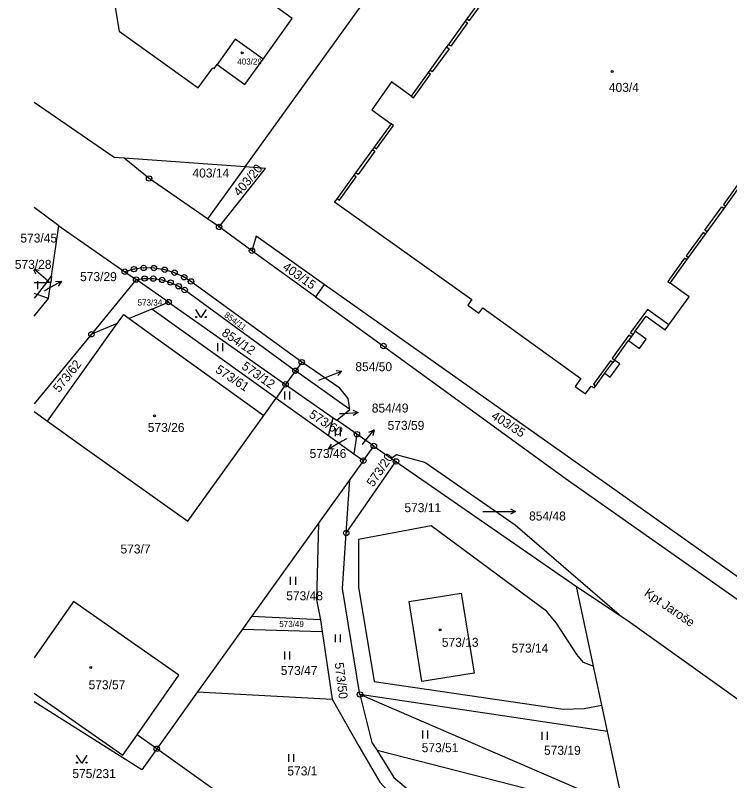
# Model space of a CAD drawing. Extents: x -737240 to -735272, y -1119606 to -1117878.
# Drawn here: x -737236.9 to -737101.6, y -1118720.4 to -1118575.4 of the extents above; entities that cross this region are included whole.
import ezdxf

# ---------------------------------------------------------------- set-up
doc = ezdxf.new("R2010")
doc.units = 0
for name, color, linetype in [('Level 1', 7, 'Continuous'), ('Level 15', 7, 'Continuous'), ('Level 16', 7, 'Continuous'), ('Level 18', 7, 'Continuous'), ('Level 19', 7, 'Continuous'), ('Level 25', 7, 'Continuous'), ('Level 4', 7, 'Continuous')]:
    doc.layers.add(name, color=color, linetype=linetype)

msp = doc.modelspace()

# ---------------------------------------------------------------- linework, layer by layer
at = {"layer": 'Level 1'}
for p, q in [((-737193.31, -1118604.16), (-737133.07, -1118520.39)), ((-737148.15, -1118571.71), (-737151.32, -1118576.1)), ((-737151.64, -1118576.55), (-737154.84, -1118580.96)), ((-737151.32, -1118576.1), (-737151.64, -1118576.55)), ((-737154.84, -1118580.96), (-737155.18, -1118581.42)), ((-737155.18, -1118581.42), (-737158.35, -1118585.81)), ((-737158.68, -1118586.26), (-737161.91, -1118590.73)), ((-737158.35, -1118585.81), (-737158.68, -1118586.26)), ((-737165.69, -1118595.96), (-737168.9, -1118600.4)), ((-737169.23, -1118600.85), (-737172.41, -1118605.26)), ((-737168.9, -1118600.4), (-737169.23, -1118600.85)), ((-737193.31, -1118604.16), (-737216.26, -1118602.47)), ((-737193.31, -1118604.16), (-737200.44, -1118614.01)), ((-737172.73, -1118605.71), (-737175.92, -1118610.13)), ((-737172.41, -1118605.26), (-737172.73, -1118605.71)), ((-737102.3, -1118611.56), (-737099.13, -1118607.18)), ((-737102.63, -1118612.02), (-737102.3, -1118611.56)), ((-737228.65, -1118615.3), (-737233.313, -1118611.841)), ((-737105.82, -1118616.43), (-737102.63, -1118612.02)), ((-737198.27, -1118615.51), (-737200.44, -1118614.01)), ((-737230, -1118624.86), (-737228.65, -1118615.3)), ((-737228.65, -1118615.3), (-737216.14, -1118623.99)), ((-737192.05, -1118620.02), (-737198.27, -1118615.51)), ((-737109.33, -1118621.28), (-737106.16, -1118616.89)), ((-737106.16, -1118616.89), (-737105.82, -1118616.43)), ((-737180.02, -1118628.74), (-737192.05, -1118620.02)), ((-737112.85, -1118626.14), (-737109.66, -1118621.73)), ((-737109.66, -1118621.73), (-737109.33, -1118621.28)), ((-737216.14, -1118623.99), (-737213.99, -1118625.48)), ((-737233.313, -1118626.039), (-737230.94, -1118626.03)), ((-737230.94, -1118626.03), (-737232.75, -1118628.29)), ((-737230.94, -1118626.03), (-737230, -1118624.86)), ((-737230.16, -1118626.04), (-737230.94, -1118626.03)), ((-737230.6, -1118629.1), (-737230.16, -1118626.04)), ((-737230, -1118624.86), (-737230.16, -1118626.04)), ((-737213.99, -1118625.48), (-737222.45, -1118635.85)), ((-737207.85, -1118629.75), (-737213.99, -1118625.48)), ((-737178.34, -1118626.41), (-737180.02, -1118628.74)), ((-737233.313, -1118628.075), (-737232.75, -1118628.29)), ((-737232.75, -1118628.29), (-737233.313, -1118628.991)), ((-737230.6, -1118629.1), (-737232.75, -1118628.29)), ((-737211.04, -1118631.08), (-737207.85, -1118629.75)), ((-737207.85, -1118629.75), (-737185.68, -1118645.33)), ((-737211.04, -1118631.08), (-737215.31, -1118632.86)), ((-737187.47, -1118647.95), (-737211.04, -1118631.08)), ((-737230.77, -1118652.31), (-737217.55, -1118633.8)), ((-737217.55, -1118633.8), (-737222.45, -1118635.85)), ((-737222.45, -1118635.85), (-737233.313, -1118649.023)), ((-737123.4, -1118640.72), (-737120.73, -1118637.03)), ((-737182.62, -1118641.13), (-737183.8, -1118642.75)), ((-737183.8, -1118642.75), (-737185.68, -1118645.33)), ((-737173.49, -1118650.1), (-737183.8, -1118642.75)), ((-737126.92, -1118645.59), (-737125.21, -1118643.22)), ((-737185.68, -1118645.33), (-737187.47, -1118647.95)), ((-737185.68, -1118645.33), (-737176.64, -1118651.66)), ((-737189.81, -1118651.21), (-737187.47, -1118647.95)), ((-737187.47, -1118647.95), (-737177.56, -1118655.03)), ((-737233.313, -1118650.471), (-737230.77, -1118652.31)), ((-737175.96, -1118652.13), (-737173.49, -1118650.1)), ((-737177.56, -1118655.03), (-737176.64, -1118651.66)), ((-737176.64, -1118651.66), (-737175.96, -1118652.13)), ((-737172.17, -1118654.78), (-737175.96, -1118652.13)), ((-737177.56, -1118655.03), (-737172.72, -1118658.5)), ((-737172.17, -1118654.78), (-737172.72, -1118658.5)), ((-737168.96, -1118657.01), (-737172.17, -1118654.78)), ((-737170.94, -1118659.78), (-737168.96, -1118657.01)), ((-737168.96, -1118657.01), (-737165.59, -1118659.35)), ((-737172.72, -1118658.5), (-737170.94, -1118659.78)), ((-737165.59, -1118659.35), (-737164.77, -1118659.92)), ((-737174.18, -1118673.49), (-737164.77, -1118659.92)), ((-737170.94, -1118659.78), (-737173.51, -1118663.36)), ((-737164.77, -1118659.92), (-737130.56, -1118683.64)), ((-737173.51, -1118663.36), (-737179.44, -1118671.64)), ((-737174.18, -1118673.49), (-737173.51, -1118663.36)), ((-737179.44, -1118671.64), (-737192.11, -1118689.31)), ((-737130.56, -1118683.64), (-737122.52, -1118688.97)), ((-737127.35, -1118698.73), (-737130.56, -1118683.64)), ((-737192.11, -1118689.31), (-737193.83, -1118691.71)), ((-737179.08, -1118689.92), (-737192.11, -1118689.31)), ((-737179.08, -1118689.92), (-737178.75, -1118692.14)), ((-737193.83, -1118691.71), (-737202.33, -1118703.57)), ((-737193.83, -1118691.71), (-737178.75, -1118692.14)), ((-737178.75, -1118692.14), (-737176.87, -1118704.97)), ((-737125.78, -1118706.13), (-737127.35, -1118698.73)), ((-737202.33, -1118703.57), (-737210.07, -1118714.36)), ((-737202.33, -1118703.57), (-737176.87, -1118704.97)), ((-737124.73, -1118711.06), (-737171.59, -1118704.08)), ((-737121.62, -1118725.66), (-737171.59, -1118704.08)), ((-737124.73, -1118711.06), (-737125.78, -1118706.13)), ((-737210.07, -1118714.36), (-737213.79, -1118711.71)), ((-737121.62, -1118725.66), (-737124.73, -1118711.06)), ((-737189.33, -1118729.14), (-737210.07, -1118714.36)), ((-737121.41, -1118726.65), (-737168.35, -1118714.71))]:
    msp.add_line(p, q, dxfattribs=at)
for points in [[(-737189.93, -1118583.71), (-737184.41, -1118576.03), (-737199.69, -1118564.94), (-737200.12, -1118562.3), (-737186.12, -1118560.03), (-737188.01, -1118548.39), (-737182.85, -1118547.56), (-737186.18, -1118526.96), (-737215.02, -1118531.57), (-737214.4, -1118535.42), (-737219.27, -1118536.23), (-737216.7, -1118552.51), (-737217.91, -1118552.7), (-737217.86, -1118553), (-737221.24, -1118553.54), (-737219.2, -1118566.32), (-737221.63, -1118570.06), (-737218.17, -1118572.81), (-737217.18, -1118578.42), (-737202.24, -1118589.17), (-737199.46, -1118585.37), (-737199.23, -1118585.53), (-737198.64, -1118584.72)], [(-737189.93, -1118583.71), (-737195.2, -1118579.93), (-737198.64, -1118584.72)], [(-737198.64, -1118584.72), (-737193.38, -1118588.51), (-737189.93, -1118583.71)], [(-737161.91, -1118590.73), (-737165.62, -1118588.06), (-737169.31, -1118593.32), (-737165.69, -1118595.96)], [(-737216.26, -1118602.47), (-737218.12, -1118602.34), (-737233.313, -1118591.922)], [(-737200.44, -1118614.01), (-737211.53, -1118606.34), (-737216.26, -1118602.47)], [(-737198.27, -1118615.51), (-737189.47, -1118604.44), (-737193.31, -1118604.16)], [(-737175.92, -1118610.13), (-737176.43, -1118610.79), (-737150.4, -1118629.29), (-737151.16, -1118630.34), (-737149.05, -1118631.87), (-737148.29, -1118630.81), (-737129.75, -1118644.23), (-737130.82, -1118645.71), (-737128.86, -1118647.13), (-737127.79, -1118645.65), (-737127.24, -1118645.99), (-737126.92, -1118645.59)], [(-737178.34, -1118626.41), (-737191.23, -1118617.29), (-737192.05, -1118620.02)], [(-737182.62, -1118641.13), (-737203.6, -1118625.84), (-737204.87, -1118625.05), (-737206.7, -1118624.18), (-737208.55, -1118623.62), (-737210.62, -1118623.3), (-737212.56, -1118623.28), (-737214.39, -1118623.51), (-737216.14, -1118623.99)], [(-737213.99, -1118625.48), (-737212.39, -1118625.28), (-737210.72, -1118625.3), (-737209.06, -1118625.55), (-737207.46, -1118626.04), (-737205.93, -1118626.74), (-737204.78, -1118627.46), (-737183.8, -1118642.75)], [(-737113.11, -1118634.05), (-737109.26, -1118628.74), (-737112.85, -1118626.14)], [(-737096.44, -1118684.35), (-737124.41, -1118664.58), (-737178.34, -1118626.41)], [(-737233.313, -1118632.413), (-737230.6, -1118629.1)], [(-737180.02, -1118628.74), (-737167.14, -1118638.07), (-737132.69, -1118663.08), (-737098.41, -1118687.2), (-737097.57, -1118687.8)], [(-737217.55, -1118633.8), (-737216.34, -1118632.11), (-737215.31, -1118632.86)], [(-737215.31, -1118632.86), (-737209.82, -1118636.84), (-737189.81, -1118651.21)], [(-737119.44, -1118635.25), (-737117.38, -1118632.4), (-737113.79, -1118635), (-737113.11, -1118634.05)], [(-737120.73, -1118637.03), (-737118.64, -1118638.54), (-737117.35, -1118636.76), (-737119.44, -1118635.25)], [(-737125.21, -1118643.22), (-737124.17, -1118643.97), (-737122.36, -1118641.47), (-737123.4, -1118640.72)], [(-737173.49, -1118650.1), (-737173.82, -1118648.01), (-737175.42, -1118646.04), (-737182.62, -1118641.13)], [(-737230.77, -1118652.31), (-737224.24, -1118656.99), (-737204.2, -1118671.26), (-737189.81, -1118651.21)], [(-737122.52, -1118688.97), (-737142.19, -1118671.99), (-737159.33, -1118660.12), (-737164.65, -1118658.71), (-737165.59, -1118659.35)], [(-737179.44, -1118671.64), (-737179.82, -1118686.15), (-737179.08, -1118689.92)], [(-737127.35, -1118698.73), (-737127.46, -1118698.72), (-737129.24, -1118698.01), (-737130.52, -1118696.5), (-737134.38, -1118690.56), (-737136.28, -1118688.27), (-737158.09, -1118672.16), (-737171.87, -1118674.72), (-737171.85, -1118683.75), (-737168.9, -1118701.59), (-737133.1, -1118706.86), (-737129.1, -1118706.7), (-737125.78, -1118706.13)], [(-737171.59, -1118704.08), (-737174.88, -1118684.02), (-737174.18, -1118673.49)], [(-737162.29, -1118686.44), (-737152.41, -1118684.86), (-737149.95, -1118700.01), (-737159.89, -1118701.64), (-737162.29, -1118686.44)], [(-737213.79, -1118711.71), (-737205.9, -1118700.43), (-737225.84, -1118686.47), (-737233.313, -1118697.141)], [(-737122.52, -1118688.97), (-737120.76, -1118690.14), (-737045.38, -1118744)], [(-737233.313, -1118703.828), (-737216.51, -1118715.6), (-737213.79, -1118711.71)], [(-737171.59, -1118704.08), (-737169.34, -1118713.14), (-737168.35, -1118714.71)], [(-737210.07, -1118714.36), (-737212.92, -1118718.33), (-737233.313, -1118705.441)], [(-737176.87, -1118704.97), (-737171.79, -1118713.84), (-737167.84, -1118720.71), (-737164.67, -1118724.07)], [(-737168.35, -1118714.71), (-737165.14, -1118719.81), (-737158.2, -1118725.63)]]:
    msp.add_lwpolyline(points, dxfattribs=at)
at = {"layer": 'Level 16'}
for points in [[(-737233.313, -1118623.485), (-737232.321, -1118623.721)], [(-737230.49, -1118625.91), (-737231.11, -1118625.39), (-737233.313, -1118623.542)], [(-737232.964, -1118624.488), (-737233.313, -1118623.683)], [(-737231.33, -1118627.6), (-737230.75, -1118627.27), (-737228.146, -1118625.78)], [(-737229.263, -1118625.843), (-737228.146, -1118625.78), (-737228.766, -1118626.71)], [(-737179.4, -1118644.52), (-737177.81, -1118643.91), (-737175.007, -1118642.84)], [(-737176.12, -1118642.729), (-737175.007, -1118642.84), (-737175.763, -1118643.664)], [(-737175.48, -1118650.86), (-737174.9, -1118650.83), (-737171.904, -1118650.673)], [(-737172.929, -1118650.226), (-737171.904, -1118650.673), (-737172.877, -1118651.225)], [(-737171.11, -1118656.71), (-737170.78, -1118656.29), (-737168.904, -1118653.949)], [(-737169.92, -1118654.417), (-737168.904, -1118653.949), (-737169.139, -1118655.042)], [(-737174.16, -1118655.65), (-737174.96, -1118656.1), (-737177.571, -1118657.578)], [(-737176.454, -1118657.52), (-737177.571, -1118657.578), (-737176.947, -1118656.65)], [(-737148.34, -1118669.42), (-737145.1, -1118669.42), (-737142.1, -1118669.425)], [(-737143.099, -1118668.923), (-737142.1, -1118669.425), (-737143.101, -1118669.923)]]:
    msp.add_lwpolyline(points, dxfattribs=at)
at = {"layer": 'Level 25'}
for p, q in [((-737232.575, -1118627.315), (-737232.575, -1118625.815)), ((-737198.577, -1118637.525), (-737198.577, -1118639.025)), ((-737197.555, -1118639.025), (-737197.555, -1118637.525)), ((-737185.877, -1118646.695), (-737185.877, -1118648.195)), ((-737184.855, -1118648.195), (-737184.855, -1118646.695)), ((-737176.277, -1118653.655), (-737176.277, -1118655.155)), ((-737175.255, -1118655.155), (-737175.255, -1118653.655)), ((-737184.777, -1118681.795), (-737184.777, -1118683.295)), ((-737183.755, -1118683.295), (-737183.755, -1118681.795)), ((-737176.297, -1118692.695), (-737176.297, -1118694.195)), ((-737175.275, -1118694.195), (-737175.275, -1118692.695)), ((-737185.867, -1118695.945), (-737185.867, -1118697.445)), ((-737184.845, -1118697.445), (-737184.845, -1118695.945)), ((-737159.727, -1118710.905), (-737159.727, -1118712.405)), ((-737158.705, -1118712.405), (-737158.705, -1118710.905)), ((-737137.107, -1118711.175), (-737137.107, -1118712.675)), ((-737136.085, -1118712.675), (-737136.085, -1118711.175)), ((-737185.117, -1118715.355), (-737185.117, -1118716.855)), ((-737184.095, -1118716.855), (-737184.095, -1118715.355))]:
    msp.add_line(p, q, dxfattribs=at)
for points in [[(-737200.7, -1118631.18), (-737201.7, -1118632.68), (-737202.7, -1118631.18)], [(-737223.29, -1118715.59), (-737224.29, -1118717.09), (-737225.29, -1118715.59)]]:
    msp.add_lwpolyline(points, dxfattribs=at)
for centre in [(-737202.6, -1118632.58), (-737200.8, -1118632.58), (-737225.19, -1118716.99), (-737223.39, -1118716.99)]:
    msp.add_circle(centre, 0.1, dxfattribs=at)
for centre, major_axis in [((-737193.89, -1118582.52), (0.18, 0)), ((-737123.81, -1118586.06), (0.18, 0)), ((-737211.53, -1118606.34), (0.516, 0)), ((-737211.53, -1118606.34), (0.0375, 0)), ((-737198.27, -1118615.51), (0.516, 0)), ((-737198.27, -1118615.51), (0.0375, 0)), ((-737192.05, -1118620.02), (0.516, 0)), ((-737192.05, -1118620.02), (0.0375, 0)), ((-737214.39, -1118623.51), (0.516, 0)), ((-737212.56, -1118623.28), (0.516, 0)), ((-737212.56, -1118623.28), (0.0375, 0)), ((-737210.62, -1118623.3), (0.516, 0)), ((-737210.62, -1118623.3), (0.0375, 0)), ((-737208.55, -1118623.62), (0.516, 0)), ((-737216.14, -1118623.99), (0.516, 0)), ((-737216.14, -1118623.99), (0.0375, 0)), ((-737214.39, -1118623.51), (0.0375, 0)), ((-737212.39, -1118625.28), (0.516, 0)), ((-737210.72, -1118625.3), (0.516, 0)), ((-737208.55, -1118623.62), (0.0375, 0)), ((-737206.7, -1118624.18), (0.516, 0)), ((-737206.7, -1118624.18), (0.0375, 0)), ((-737204.87, -1118625.05), (0.516, 0)), ((-737213.99, -1118625.48), (0.516, 0)), ((-737213.99, -1118625.48), (0.0375, 0)), ((-737212.39, -1118625.28), (0.0375, 0)), ((-737210.72, -1118625.3), (0.0375, 0)), ((-737209.06, -1118625.55), (0.516, 0)), ((-737209.06, -1118625.55), (0.0375, 0)), ((-737207.46, -1118626.04), (0.516, 0)), ((-737207.46, -1118626.04), (0.0375, 0)), ((-737205.93, -1118626.74), (0.516, 0)), ((-737204.87, -1118625.05), (0.0375, 0)), ((-737203.6, -1118625.84), (0.516, 0)), ((-737203.6, -1118625.84), (0.0375, 0)), ((-737205.93, -1118626.74), (0.0375, 0)), ((-737204.78, -1118627.46), (0.516, 0)), ((-737204.78, -1118627.46), (0.0375, 0)), ((-737207.85, -1118629.75), (0.516, 0)), ((-737207.85, -1118629.75), (0.0375, 0)), ((-737222.45, -1118635.85), (0.516, 0)), ((-737222.45, -1118635.85), (0.0375, 0)), ((-737167.14, -1118638.07), (0.516, 0)), ((-737167.14, -1118638.07), (0.0375, 0)), ((-737182.62, -1118641.13), (0.516, 0)), ((-737182.62, -1118641.13), (0.0375, 0)), ((-737183.8, -1118642.75), (0.516, 0)), ((-737183.8, -1118642.75), (0.0375, 0)), ((-737185.68, -1118645.33), (0.516, 0)), ((-737185.68, -1118645.33), (0.0375, 0)), ((-737210.5, -1118651.31), (0.18, 0)), ((-737172.17, -1118654.78), (0.516, 0)), ((-737172.17, -1118654.78), (0.0375, 0)), ((-737168.96, -1118657.01), (0.516, 0)), ((-737168.96, -1118657.01), (0.0375, 0)), ((-737170.94, -1118659.78), (0.516, 0)), ((-737164.77, -1118659.92), (0.516, 0)), ((-737170.94, -1118659.78), (0.0375, 0)), ((-737164.77, -1118659.92), (0.0375, 0)), ((-737174.18, -1118673.49), (0.516, 0)), ((-737174.18, -1118673.49), (0.0375, 0)), ((-737156.42, -1118691.82), (0.18, 0)), ((-737222.59, -1118698.98), (0.18, 0)), ((-737171.59, -1118704.08), (0.516, 0)), ((-737171.59, -1118704.08), (0.0375, 0)), ((-737210.07, -1118714.36), (0.516, 0)), ((-737210.07, -1118714.36), (0.0375, 0))]:
    msp.add_ellipse(centre, major_axis=major_axis, ratio=0.9848078, dxfattribs=at)
at = {"layer": 'Level 4'}
for p, q in [((-737120.21, -1118636.32), (-737120.73, -1118637.03)), ((-737119.88, -1118635.87), (-737120.21, -1118636.32)), ((-737119.44, -1118635.25), (-737119.88, -1118635.87)), ((-737123.4, -1118640.72), (-737123.72, -1118641.17)), ((-737125.21, -1118643.22), (-737123.72, -1118641.17))]:
    msp.add_line(p, q, dxfattribs=at)
for points in [[(-737151.32, -1118576.1), (-737150.87, -1118576.42), (-737147.7, -1118572.04), (-737148.15, -1118571.71)], [(-737151.64, -1118576.55), (-737151.2, -1118576.88), (-737154.39, -1118581.29), (-737154.84, -1118580.96)], [(-737155.18, -1118581.42), (-737154.72, -1118581.75), (-737157.9, -1118586.14), (-737158.35, -1118585.81)], [(-737161.91, -1118590.73), (-737161.46, -1118591.06), (-737158.23, -1118586.59), (-737158.68, -1118586.26)], [(-737168.9, -1118600.4), (-737168.45, -1118600.73), (-737165.24, -1118596.29), (-737165.69, -1118595.96)], [(-737169.23, -1118600.85), (-737168.77, -1118601.18), (-737171.95, -1118605.59), (-737172.41, -1118605.26)], [(-737175.92, -1118610.13), (-737175.47, -1118610.45), (-737172.28, -1118606.03), (-737172.73, -1118605.71)], [(-737099.13, -1118607.18), (-737099.57, -1118606.86), (-737102.75, -1118611.24), (-737102.3, -1118611.56)], [(-737105.82, -1118616.43), (-737106.27, -1118616.11), (-737103.07, -1118611.7), (-737102.63, -1118612.02)], [(-737106.16, -1118616.89), (-737106.6, -1118616.57), (-737109.77, -1118620.96), (-737109.33, -1118621.28)], [(-737109.66, -1118621.73), (-737110.1, -1118621.41), (-737113.29, -1118625.82), (-737112.85, -1118626.14)], [(-737113.11, -1118634.05), (-737117.14, -1118631.13), (-737120.33, -1118635.54), (-737119.88, -1118635.87)], [(-737120.21, -1118636.32), (-737120.66, -1118636), (-737123.84, -1118640.4), (-737123.4, -1118640.72)], [(-737123.72, -1118641.17), (-737124.16, -1118640.85), (-737127.36, -1118645.27), (-737126.92, -1118645.59)]]:
    msp.add_lwpolyline(points, dxfattribs=at)

# ---------------------------------------------------------------- texts
at = {"layer": 'Level 15'}
msp.add_text('Kpt Jaroše', height=1.7, rotation=325.61181, dxfattribs=at).set_placement((-737117.88, -1118685.23))
at = {"layer": 'Level 16'}
for s, p in [('573/28', (-737236.96, -1118623.46)), ('573/29', (-737224.6, -1118625.78)), ('854/50', (-737172.46, -1118642.84)), ('854/49', (-737169.35, -1118650.67)), ('573/59', (-737166.35, -1118653.95)), ('573/46', (-737181.12, -1118659.28)), ('854/48', (-737139.55, -1118671.12))]:
    msp.add_text(s, height=1.7, dxfattribs=at).set_placement(p)
at = {"layer": 'Level 18'}
for s, height, p in [('403/14', 1.7, (-737203.31, -1118606.15)), ('573/45', 1.7, (-737235.91, -1118618.47)), ('573/28', 0.1, (-737230.49, -1118625.91)), ('573/29', 0.1, (-737231.18, -1118627.6)), ('573/34', 1.14, (-737213.71, -1118630.4)), ('854/50', 0.1, (-737179.25, -1118644.52)), ('854/49', 0.1, (-737175.33, -1118650.86)), ('573/46', 0.1, (-737174.01, -1118655.65)), ('573/59', 0.1, (-737170.96, -1118656.71)), ('573/11', 1.7, (-737163.17, -1118669.54)), ('854/48', 0.1, (-737148.19, -1118669.42)), ('573/7', 1.7, (-737216.945, -1118677.37)), ('573/48', 1.7, (-737185.55, -1118686.23)), ('573/49', 1.14, (-737186.87, -1118691.28)), ('573/14', 1.7, (-737142.86, -1118696.14)), ('573/47', 1.7, (-737186.59, -1118700.38)), ('573/51', 1.7, (-737159.89, -1118715)), ('573/19', 1.7, (-737136.72, -1118715.5)), ('575/231', 1.7, (-737226.055, -1118719.91)), ('573/1', 1.7, (-737185.335, -1118719.41))]:
    msp.add_text(s, height=height, dxfattribs=at).set_placement(p)
for s, height, rotation, p in [('403/20', 1.7, 49.77432, (-737194.42, -1118609.84)), ('403/15', 1.7, 324.90261, (-737186.39, -1118623.45)), ('854/11', 1.14, 323.79057, (-737197.4, -1118632.44)), ('854/12', 1.7, 325.96668, (-737197.92, -1118635.96)), ('573/62', 1.7, 51.51114, (-737228.56, -1118647)), ('573/61', 1.7, 326.71404, (-737199.11, -1118642.94)), ('573/12', 1.7, 324.99657, (-737194.15, -1118642.27)), ('573/60', 1.7, 327.08376, (-737181.38, -1118651.44)), ('403/35', 1.7, 327.52341, (-737146.85, -1118651.72)), ('573/20', 1.7, 55.95408, (-737169.07, -1118664.89)), ('573/50', 1.7, 276.8022, (-737176.378, -1118698.092))]:
    msp.add_text(s, height=height, rotation=rotation, dxfattribs=at).set_placement(p)
at = {"layer": 'Level 19'}
for s, height, p in [('403/29', 1.14, (-737194.825, -1118584.76)), ('403/4', 1.7, (-737124.44, -1118589.93)), ('573/26', 1.7, (-737211.775, -1118654.35)), ('573/13', 1.7, (-737156.08, -1118695.05)), ('573/57', 1.7, (-737222.985, -1118703.08))]:
    msp.add_text(s, height=height, dxfattribs=at).set_placement(p)

doc.saveas('drawing.dxf')
